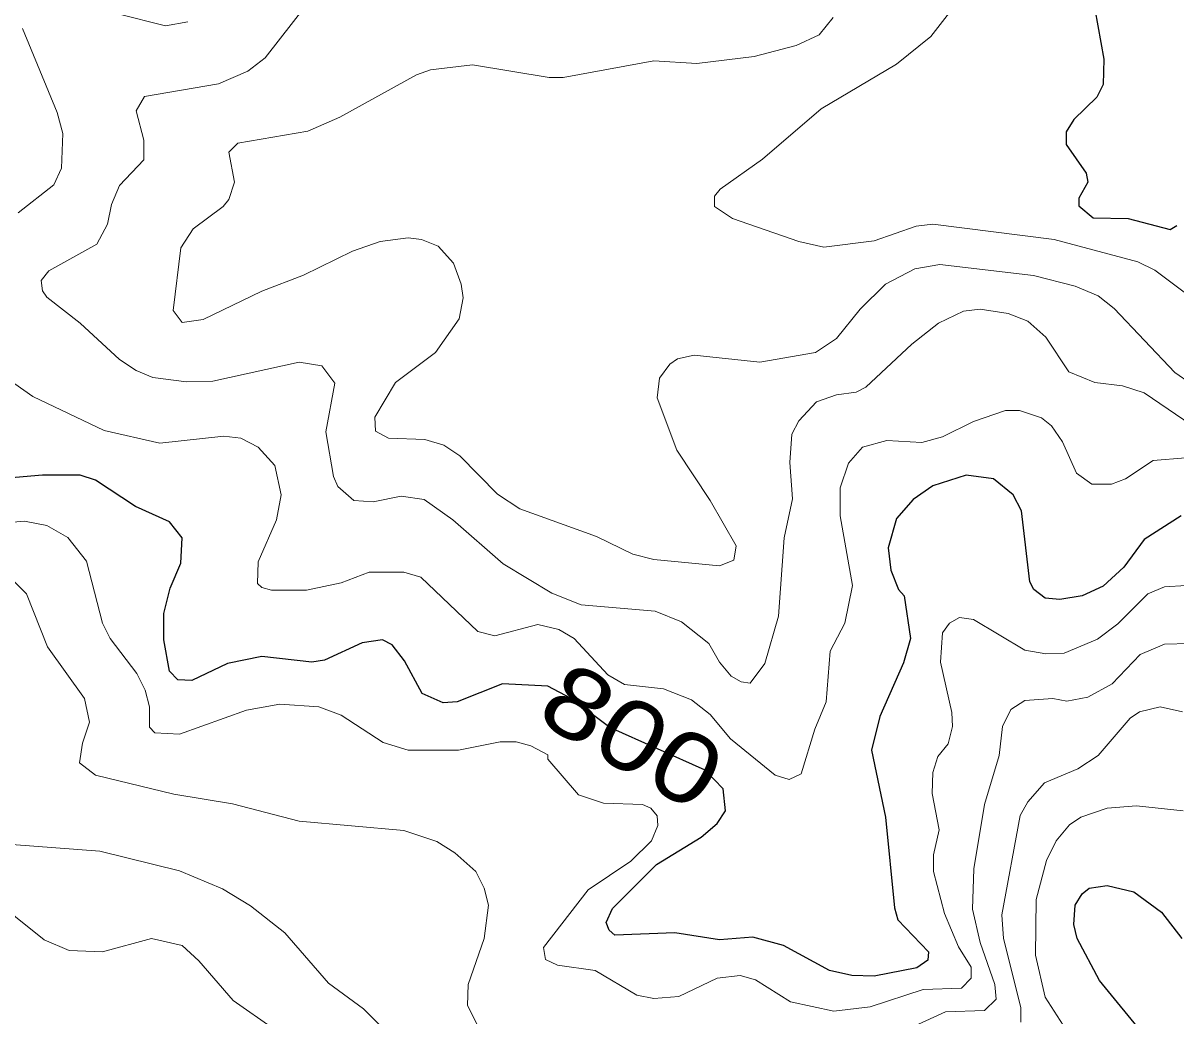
# Model space of a CAD drawing. Extents: x 265 to 291.4, y 7731.5 to 7759.6.
# Drawn here: x 284.024 to 285.338, y 7747.826 to 7748.958 of the extents above; entities that cross this region are included whole.
import ezdxf
from ezdxf.enums import TextEntityAlignment as Align

# ---------------------------------------------------------------- set-up
doc = ezdxf.new("R2010")
doc.units = 0
doc.header["$LTSCALE"] = 0.032
for name, color, linetype, lineweight in [('1', 7, 'Continuous', 25), ('2', 7, 'Continuous', 13), ('61', 7, 'Continuous', 13)]:
    doc.layers.add(name, color=color, linetype=linetype, lineweight=lineweight)

msp = doc.modelspace()

# ---------------------------------------------------------------- linework, layer by layer
at = {"layer": '1'}
for points in [[(285.1933, 7749.2078), (285.2219, 7749.1966), (285.2529, 7749.172), (285.2617, 7749.1561), (285.2728, 7749.1028), (285.2704, 7749.0742), (285.2458, 7748.9739), (285.2561, 7748.9167), (285.2553, 7748.888), (285.2481, 7748.8737), (285.2219, 7748.8482), (285.2131, 7748.8339), (285.2131, 7748.8196), (285.2362, 7748.787), (285.2378, 7748.7767), (285.2275, 7748.7584), (285.2275, 7748.7496), (285.2442, 7748.7361), (285.284, 7748.7353), (285.3317, 7748.7225), (285.3396, 7748.7273)], [(284.1917, 7748.3137), (284.2037, 7748.3423), (284.2053, 7748.371), (284.1909, 7748.3893), (284.152, 7748.4067), (284.1066, 7748.437), (284.0891, 7748.4425), (284.0462, 7748.4425), (283.9539, 7748.4346)], [(285.3444, 7748.3964), (285.3023, 7748.3693), (285.2791, 7748.3376), (285.2553, 7748.3161), (285.2315, 7748.3049), (285.206, 7748.3009), (285.1893, 7748.3025), (285.1765, 7748.3121), (285.1718, 7748.3208), (285.1622, 7748.402), (285.1527, 7748.4203), (285.1304, 7748.4386), (285.0994, 7748.4425), (285.0612, 7748.4306), (285.0389, 7748.4147), (285.0198, 7748.3932), (285.0103, 7748.3598), (285.0135, 7748.3344), (285.0222, 7748.3121), (285.0286, 7748.3049), (285.0357, 7748.2564), (285.0278, 7748.2286), (285.0007, 7748.1673), (284.9912, 7748.1291), (285.0071, 7748.0528), (285.0174, 7747.9494), (285.0214, 7747.9358), (285.0564, 7747.8992), (285.0556, 7747.8897), (285.0429, 7747.8809), (284.9944, 7747.8714), (284.9689, 7747.8722), (284.9435, 7747.8777), (284.891, 7747.9064), (284.856, 7747.9159), (284.8178, 7747.9127), (284.7669, 7747.9207), (284.6985, 7747.9183), (284.6921, 7747.9239), (284.6889, 7747.9326), (284.6961, 7747.9485), (284.7462, 7747.9987), (284.7971, 7748.0297), (284.8154, 7748.0456), (284.8249, 7748.0599), (284.8222, 7748.0851), (284.8017, 7748.1064), (284.6928, 7748.1549), (284.6489, 7748.1881), (284.6224, 7748.202), (284.5704, 7748.2047), (284.5187, 7748.184), (284.5028, 7748.1832), (284.4789, 7748.1936), (284.459, 7748.231), (284.4447, 7748.2492), (284.4336, 7748.2548), (284.4105, 7748.2516), (284.3676, 7748.2317), (284.3532, 7748.2293), (284.296, 7748.2357), (284.257, 7748.2277)], [(284.257, 7748.2277), (284.2164, 7748.2086), (284.2005, 7748.2094), (284.1909, 7748.219), (284.1846, 7748.2548), (284.1846, 7748.285), (284.1917, 7748.3137)], [(285.2219, 7747.9303), (285.2235, 7747.9525), (285.2314, 7747.9653), (285.2394, 7747.9716), (285.2601, 7747.9748), (285.2903, 7747.9676), (285.3221, 7747.9445)], [(285.3221, 7747.9445), (285.3452, 7747.9144)], [(285.3046, 7747.8014), (285.2513, 7747.8666), (285.2259, 7747.9144), (285.2219, 7747.9303)]]:
    msp.add_lwpolyline(points, dxfattribs=at)
at = {"layer": '2'}
for points in [[(284.3469, 7748.9787), (284.2999, 7748.9183), (284.2801, 7748.9031), (284.2466, 7748.8888), (284.1623, 7748.8745), (284.1528, 7748.8578), (284.1615, 7748.8244), (284.1615, 7748.8021), (284.1337, 7748.7727), (284.1249, 7748.7512), (284.1202, 7748.7289), (284.1082, 7748.7058), (284.0533, 7748.6756), (284.0446, 7748.6645), (284.0462, 7748.6526), (284.0509, 7748.6454), (284.0891, 7748.616), (284.1337, 7748.5746), (284.1528, 7748.5619), (284.1719, 7748.5539), (284.2101, 7748.5491), (284.2403, 7748.5499), (284.3389, 7748.5714), (284.3644, 7748.5674), (284.3795, 7748.5476), (284.3691, 7748.4919), (284.3779, 7748.441), (284.3827, 7748.4298), (284.401, 7748.4139), (284.4232, 7748.4123), (284.4551, 7748.4187), (284.4813, 7748.4147), (284.5139, 7748.3916), (284.5712, 7748.3415), (284.6269, 7748.3081), (284.6603, 7748.2946), (284.7446, 7748.2874), (284.7748, 7748.2755), (284.8058, 7748.2508), (284.8178, 7748.2294), (284.8313, 7748.2134), (284.8425, 7748.2071), (284.8528, 7748.2055), (284.8695, 7748.2278), (284.8854, 7748.2819), (284.8918, 7748.371), (284.9013, 7748.4155), (284.8981, 7748.4569), (284.9005, 7748.4895), (284.9085, 7748.5046), (284.9284, 7748.5261), (284.9514, 7748.534), (284.9737, 7748.5372)], [(285.0883, 7748.9803), (285.0588, 7748.9429), (285.0199, 7748.9111), (284.9339, 7748.8602), (284.8671, 7748.8029), (284.8186, 7748.7687), (284.8122, 7748.7607), (284.8122, 7748.7488), (284.8329, 7748.7353), (284.9085, 7748.709), (284.9371, 7748.7027), (284.9944, 7748.7098), (285.0421, 7748.7265), (285.0612, 7748.7289), (285.1996, 7748.7114), (285.2951, 7748.686), (285.3142, 7748.6764), (285.3524, 7748.6478)], [(284.1321, 7748.9684), (284.1862, 7748.9548), (284.2116, 7748.9596)], [(285.3556, 7748.5468), (285.3373, 7748.5595), (285.268, 7748.6327), (285.2497, 7748.647), (285.2235, 7748.6581), (285.1758, 7748.6701), (285.0692, 7748.6828), (285.0405, 7748.678), (285.0071, 7748.6605), (284.9785, 7748.6319), (284.9514, 7748.5985), (284.9276, 7748.5826), (284.8639, 7748.5714), (284.7892, 7748.5794), (284.7701, 7748.5754), (284.7613, 7748.569), (284.7494, 7748.5531), (284.747, 7748.5308), (284.7693, 7748.4712), (284.8074, 7748.4139), (284.8369, 7748.3622), (284.8345, 7748.3455), (284.8178, 7748.3391), (284.743, 7748.3463), (284.7192, 7748.3527), (284.6778, 7748.3725), (284.5903, 7748.4044), (284.5648, 7748.4211), (284.5219, 7748.4648), (284.5036, 7748.4767), (284.4821, 7748.4831), (284.4407, 7748.4847), (284.4256, 7748.4927), (284.4248, 7748.5086), (284.4487, 7748.5484), (284.494, 7748.5825), (284.5211, 7748.6207), (284.5258, 7748.6446), (284.5235, 7748.6605), (284.5147, 7748.6844), (284.4972, 7748.7035), (284.4781, 7748.7114), (284.463, 7748.713), (284.4312, 7748.709), (284.3994, 7748.6979), (284.3437, 7748.6708), (284.296, 7748.6525), (284.2291, 7748.6199), (284.2053, 7748.6168), (284.1949, 7748.6303), (284.2037, 7748.7019), (284.218, 7748.7233), (284.2522, 7748.7488), (284.2586, 7748.7568), (284.2649, 7748.7767), (284.2586, 7748.8109), (284.2689, 7748.8212), (284.3485, 7748.8347), (284.3851, 7748.8506), (284.4726, 7748.8991), (284.4885, 7748.9047), (284.5362, 7748.9103), (284.6237, 7748.896), (284.6396, 7748.896), (284.743, 7748.9151), (284.7923, 7748.9119), (284.8576, 7748.9198), (284.9053, 7748.9326), (284.9316, 7748.9445), (284.9475, 7748.9644)], [(284.0183, 7748.7416), (284.0589, 7748.7735), (284.0676, 7748.7926), (284.0692, 7748.8323), (284.0629, 7748.8562), (284.0231, 7748.9517)], [(284.9737, 7748.5372), (284.9849, 7748.5428), (285.0374, 7748.5921), (285.0676, 7748.616), (285.0962, 7748.6295), (285.1153, 7748.6319), (285.1471, 7748.6271)], [(285.1471, 7748.6271), (285.1694, 7748.6183), (285.1901, 7748.6001), (285.2163, 7748.5603), (285.2458, 7748.5483), (285.2776, 7748.5444), (285.3022, 7748.5364), (285.3651, 7748.4935)], [(284.9268, 7748.153), (284.9109, 7748.1021), (284.8974, 7748.0957), (284.8814, 7748.1005), (284.8305, 7748.1419), (284.8074, 7748.1697), (284.786, 7748.1864), (284.7542, 7748.1991), (284.7096, 7748.2039), (284.6905, 7748.215), (284.6523, 7748.2564), (284.6348, 7748.2667), (284.611, 7748.2723), (284.5617, 7748.2596), (284.5426, 7748.2643), (284.4773, 7748.3264), (284.4582, 7748.332), (284.4185, 7748.332), (284.3867, 7748.32), (284.3469, 7748.3113), (284.3071, 7748.3113), (284.296, 7748.3145), (284.2912, 7748.3192), (284.292, 7748.3439), (284.3127, 7748.3916), (284.3182, 7748.4203), (284.3111, 7748.4537), (284.292, 7748.4744), (284.2721, 7748.4847), (284.253, 7748.4871), (284.1798, 7748.4791), (284.1162, 7748.4935), (284.035, 7748.5324), (283.977, 7748.573)], [(285.3492, 7748.4624), (285.3126, 7748.4592), (285.2808, 7748.4386), (285.2649, 7748.4322), (285.2426, 7748.4322), (285.2251, 7748.4449), (285.2092, 7748.4807), (285.1964, 7748.499), (285.1853, 7748.5078), (285.1599, 7748.5165), (285.144, 7748.5165), (285.1074, 7748.5038), (285.0724, 7748.4863), (285.0485, 7748.4799), (285.0087, 7748.4823), (284.9809, 7748.4744), (284.965, 7748.4561), (284.9554, 7748.4282)], [(284.9554, 7748.4282), (284.9554, 7748.3964), (284.9697, 7748.3169), (284.961, 7748.2739), (284.9443, 7748.2421), (284.9395, 7748.184), (284.9268, 7748.153)], [(283.9778, 7748.3861), (284.0255, 7748.39), (284.051, 7748.3853), (284.0748, 7748.3717), (284.0963, 7748.3447), (284.1146, 7748.2739), (284.1233, 7748.2564), (284.1536, 7748.2166), (284.1631, 7748.1975), (284.1679, 7748.1785), (284.1679, 7748.1554), (284.1742, 7748.149), (284.2021, 7748.1474), (284.2785, 7748.1745), (284.3166, 7748.1816), (284.3612, 7748.1784), (284.3867, 7748.1689), (284.4344, 7748.1379), (284.463, 7748.1291), (284.5203, 7748.1291), (284.568, 7748.1387), (284.5863, 7748.1387), (284.603, 7748.1339), (284.6221, 7748.1236), (284.6221, 7748.1188), (284.6571, 7748.0782), (284.6858, 7748.0687), (284.7303, 7748.0671), (284.7398, 7748.0631), (284.747, 7748.0543), (284.7478, 7748.0432), (284.7406, 7748.0257), (284.7168, 7748.0026), (284.6683, 7747.97), (284.6173, 7747.904), (284.6197, 7747.8905), (284.6333, 7747.8841), (284.6762, 7747.8777), (284.7239, 7747.8499), (284.743, 7747.8459), (284.7717, 7747.8483), (284.8154, 7747.869), (284.8417, 7747.8722), (284.8592, 7747.8674), (284.8989, 7747.842), (284.9483, 7747.8316), (284.9896, 7747.8364), (285.0501, 7747.8563), (285.0938, 7747.8579), (285.105, 7747.869), (285.105, 7747.8817), (285.0906, 7747.9048), (285.0747, 7747.943), (285.062, 7747.9907), (285.062, 7748.0098), (285.0684, 7748.0384), (285.0604, 7748.0798), (285.0612, 7748.1037), (285.0668, 7748.122), (285.0787, 7748.1363), (285.0835, 7748.1562), (285.0827, 7748.1721), (285.07, 7748.2294), (285.0723, 7748.2628), (285.0803, 7748.2739), (285.0915, 7748.2803), (285.1074, 7748.2779)], [(284.5616, 7747.7767), (284.5306, 7747.838), (284.5314, 7747.8619), (284.5497, 7747.9144), (284.5545, 7747.9525), (284.5497, 7747.9716), (284.5402, 7747.9907), (284.5163, 7748.0122), (284.4956, 7748.0249), (284.4582, 7748.0376), (284.3389, 7748.048), (284.2626, 7748.0679), (284.1957, 7748.079), (284.1066, 7748.1005), (284.0883, 7748.1148), (284.0915, 7748.1371), (284.0995, 7748.161), (284.0939, 7748.188), (284.0517, 7748.2469), (284.0279, 7748.3073), (284.004, 7748.3312)], [(285.1074, 7748.2779), (285.1662, 7748.2429), (285.1901, 7748.2389), (285.2108, 7748.2397), (285.249, 7748.2556), (285.272, 7748.2731), (285.3062, 7748.3073)], [(285.3062, 7748.3073), (285.3253, 7748.3153), (285.35, 7748.3169)], [(285.354, 7748.2508), (285.3253, 7748.25), (285.2975, 7748.2381), (285.2657, 7748.2047), (285.2378, 7748.1896), (285.214, 7748.1848), (285.198, 7748.188), (285.1662, 7748.1856), (285.1503, 7748.1753), (285.1408, 7748.1562), (285.1368, 7748.1228), (285.1201, 7748.0671), (285.1081, 7747.9939), (285.1066, 7747.9478), (285.1153, 7747.9096), (285.132, 7747.8619), (285.1336, 7747.8451), (285.1201, 7747.8324), (285.0755, 7747.8308), (285.0135, 7747.8022)], [(285.1614, 7747.8189), (285.1614, 7747.8356), (285.1416, 7747.9144), (285.14, 7747.9414), (285.1606, 7748.0544), (285.1694, 7748.0703), (285.1885, 7748.0917), (285.2267, 7748.1076), (285.2497, 7748.1228), (285.2863, 7748.1657), (285.2967, 7748.1729), (285.3206, 7748.1784), (285.346, 7748.1729)], [(284.3103, 7747.8109), (284.2633, 7747.8435), (284.2244, 7747.8889), (284.2053, 7747.9064), (284.1703, 7747.9143), (284.1146, 7747.8992), (284.0764, 7747.9008), (284.0478, 7747.9127), (284.0152, 7747.939), (283.9817, 7747.9732), (283.9571, 7747.9875), (283.8767, 7747.9971), (283.8704, 7748.005), (283.8775, 7748.083), (283.8831, 7748.1053), (283.9006, 7748.1371)], [(285.3468, 7748.0599), (285.2935, 7748.0655), (285.2601, 7748.0631), (285.2299, 7748.0527), (285.2171, 7748.044), (285.202, 7748.0257), (285.1909, 7748.0034), (285.1789, 7747.9589), (285.1781, 7747.8953), (285.1893, 7747.8475), (285.21, 7747.8157)], [(284.0112, 7748.0217), (284.1114, 7748.0138), (284.2021, 7747.9915), (284.2514, 7747.9708), (284.2832, 7747.9517), (284.3222, 7747.9207), (284.3723, 7747.8634), (284.4121, 7747.834), (284.4328, 7747.8133)]]:
    msp.add_lwpolyline(points, dxfattribs=at)

# ---------------------------------------------------------------- texts
at = {"layer": '61', "width": 1.2}
msp.add_text('800', height=0.08, rotation=329.731, dxfattribs=at).set_placement((284.6983, 7748.1108), align=Align.CENTER)

doc.saveas('drawing.dxf')
